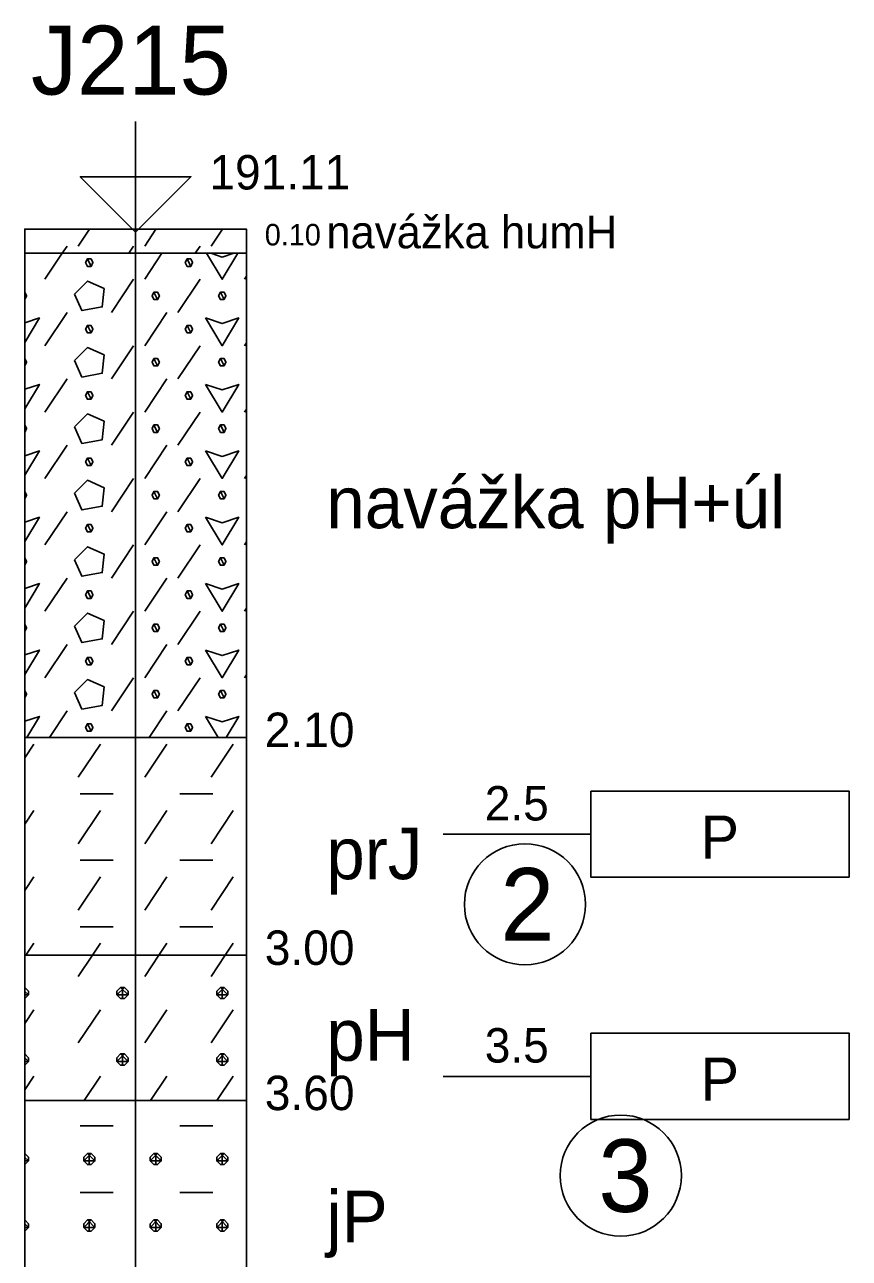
# Model space of a CAD drawing. Extents: x 3042 to 4120, y 576 to 2694.
# Drawn here: x 3710.06 to 3727.08, y 1031.63 to 1057.11 of the extents above; entities that cross this region are included whole.
import ezdxf

# ---------------------------------------------------------------- set-up
doc = ezdxf.new("R2010")
doc.units = 0
for name, color, linetype in [('15', 7, 'Continuous'), ('16', 7, 'Continuous'), ('17', 7, 'Continuous'), ('18', 7, 'Continuous'), ('51', 7, 'Continuous'), ('52', 7, 'Continuous'), ('53', 7, 'Continuous'), ('56', 7, 'Continuous'), ('62', 7, 'Continuous'), ('rozhraní', 7, 'Continuous')]:
    doc.layers.add(name, color=color, linetype=linetype)

msp = doc.modelspace()

# ---------------------------------------------------------------- linework, layer by layer
at = {"layer": '15'}
msp.add_lwpolyline([(3712.347, 1055.113), (3712.347, 1052.827), (3711.204, 1053.97), (3713.49, 1053.97), (3712.347, 1052.827)], dxfattribs=at)
at = {"layer": '18'}
msp.add_line((3712.347, 1007.89), (3712.347, 1052.89), dxfattribs=at)
at = {"layer": '51'}
for p, q in [((3711.163, 1052.539), (3711.397, 1052.89)), ((3712.535, 1052.539), (3712.768, 1052.89)), ((3713.906, 1052.539), (3714.14, 1052.89)), ((3710.477, 1051.854), (3710.835, 1052.39)), ((3710.835, 1052.39), (3710.934, 1052.539)), ((3712.206, 1052.39), (3712.306, 1052.539)), ((3712.535, 1051.854), (3712.892, 1052.39)), ((3713.578, 1052.39), (3713.678, 1052.539)), ((3714.592, 1051.854), (3714.633, 1051.915)), ((3711.849, 1051.168), (3712.306, 1051.854)), ((3713.22, 1051.168), (3713.678, 1051.854)), ((3710.058, 1051.435), (3710.058, 1051.435)), ((3710.477, 1050.482), (3710.934, 1051.168)), ((3712.535, 1050.482), (3712.992, 1051.168)), ((3711.849, 1049.796), (3712.306, 1050.482)), ((3713.22, 1049.796), (3713.678, 1050.482)), ((3714.592, 1050.482), (3714.633, 1050.543)), ((3710.058, 1050.063), (3710.058, 1050.063)), ((3710.477, 1049.11), (3710.934, 1049.796)), ((3712.535, 1049.11), (3712.992, 1049.796)), ((3711.849, 1048.425), (3712.306, 1049.11)), ((3713.22, 1048.425), (3713.678, 1049.11)), ((3714.592, 1049.11), (3714.633, 1049.171)), ((3710.058, 1048.691), (3710.058, 1048.691)), ((3710.477, 1047.739), (3710.934, 1048.425)), ((3712.535, 1047.739), (3712.992, 1048.425)), ((3714.592, 1047.739), (3714.633, 1047.8)), ((3711.849, 1047.053), (3712.306, 1047.739)), ((3713.22, 1047.053), (3713.678, 1047.739)), ((3710.058, 1047.32), (3710.058, 1047.32)), ((3710.477, 1046.367), (3710.934, 1047.053)), ((3712.535, 1046.367), (3712.992, 1047.053)), ((3711.849, 1045.681), (3712.306, 1046.367)), ((3713.22, 1045.681), (3713.678, 1046.367)), ((3714.592, 1046.367), (3714.633, 1046.428)), ((3710.058, 1045.948), (3710.058, 1045.948)), ((3710.477, 1044.996), (3710.934, 1045.681)), ((3712.535, 1044.996), (3712.992, 1045.681)), ((3711.849, 1044.31), (3712.306, 1044.996)), ((3713.22, 1044.31), (3713.678, 1044.996)), ((3714.592, 1044.996), (3714.633, 1045.057)), ((3710.058, 1044.577), (3710.058, 1044.577)), ((3710.477, 1043.624), (3710.934, 1044.31)), ((3712.535, 1043.624), (3712.992, 1044.31)), ((3711.849, 1042.938), (3712.306, 1043.624)), ((3713.22, 1042.938), (3713.678, 1043.624)), ((3714.592, 1043.624), (3714.633, 1043.685)), ((3710.058, 1043.205), (3710.058, 1043.205)), ((3710.569, 1042.39), (3710.934, 1042.938)), ((3712.626, 1042.39), (3712.992, 1042.938)), ((3713.792, 1042.824), (3714.052, 1042.39)), ((3710.061, 1041.971), (3710.249, 1042.252)), ((3711.163, 1041.567), (3711.62, 1042.252)), ((3712.535, 1041.567), (3712.992, 1042.252)), ((3713.906, 1041.567), (3714.363, 1042.252)), ((3711.201, 1041.224), (3711.887, 1041.224)), ((3713.259, 1041.224), (3713.944, 1041.224)), ((3710.061, 1040.599), (3710.249, 1040.881)), ((3711.163, 1040.195), (3711.62, 1040.881)), ((3712.535, 1040.195), (3712.992, 1040.881)), ((3713.906, 1040.195), (3714.363, 1040.881)), ((3711.201, 1039.852), (3711.887, 1039.852)), ((3713.259, 1039.852), (3713.944, 1039.852)), ((3710.061, 1039.227), (3710.249, 1039.509)), ((3711.163, 1038.823), (3711.62, 1039.509)), ((3712.535, 1038.823), (3712.992, 1039.509)), ((3713.906, 1038.823), (3714.363, 1039.509)), ((3711.201, 1038.481), (3711.887, 1038.481)), ((3713.259, 1038.481), (3713.944, 1038.481)), ((3710.084, 1037.89), (3710.249, 1038.138)), ((3711.455, 1037.89), (3711.62, 1038.138)), ((3712.827, 1037.89), (3712.992, 1038.138)), ((3714.198, 1037.89), (3714.363, 1038.138)), ((3711.163, 1037.452), (3711.455, 1037.89)), ((3712.535, 1037.452), (3712.827, 1037.89)), ((3713.906, 1037.452), (3714.198, 1037.89)), ((3710.058, 1037.223), (3710.058, 1037.223)), ((3712.077, 1036.995), (3712.077, 1037.223)), ((3714.135, 1036.995), (3714.135, 1037.223)), ((3710.061, 1036.484), (3710.249, 1036.766)), ((3711.163, 1036.08), (3711.62, 1036.766)), ((3712.535, 1036.08), (3712.992, 1036.766)), ((3713.906, 1036.08), (3714.363, 1036.766)), ((3710.058, 1035.852), (3710.058, 1035.852)), ((3712.077, 1035.623), (3712.077, 1035.852)), ((3714.135, 1035.623), (3714.135, 1035.852)), ((3710.061, 1035.113), (3710.249, 1035.394)), ((3711.284, 1034.89), (3711.62, 1035.394)), ((3712.656, 1034.89), (3712.992, 1035.394)), ((3714.027, 1034.89), (3714.363, 1035.394)), ((3711.201, 1034.366), (3711.887, 1034.366)), ((3713.259, 1034.366), (3713.944, 1034.366)), ((3710.058, 1033.794), (3710.058, 1033.794)), ((3711.392, 1033.566), (3711.392, 1033.794)), ((3712.763, 1033.566), (3712.763, 1033.794)), ((3714.135, 1033.566), (3714.135, 1033.794)), ((3711.201, 1032.994), (3711.887, 1032.994)), ((3713.259, 1032.994), (3713.944, 1032.994)), ((3710.058, 1032.423), (3710.058, 1032.423)), ((3711.392, 1032.194), (3711.392, 1032.423)), ((3712.763, 1032.194), (3712.763, 1032.423)), ((3714.135, 1032.194), (3714.135, 1032.423))]:
    msp.add_line(p, q, dxfattribs=at)
for points in [[(3710.061, 1052.39), (3714.633, 1052.39), (3714.633, 1052.89), (3710.061, 1052.89)], [(3710.061, 1042.39), (3714.633, 1042.39), (3714.633, 1052.39), (3710.061, 1052.39)], [(3710.061, 1037.89), (3714.633, 1037.89), (3714.633, 1042.39), (3710.061, 1042.39)], [(3710.061, 1034.89), (3714.633, 1034.89), (3714.633, 1037.89), (3710.061, 1037.89)], [(3710.061, 1030.39), (3714.633, 1030.39), (3714.633, 1034.89), (3710.061, 1034.89)]]:
    msp.add_lwpolyline(points, close=True, dxfattribs=at)
for points in [[(3713.813, 1052.39), (3714.135, 1051.854), (3714.457, 1052.39)], [(3714.372, 1052.39), (3714.135, 1052.311), (3713.897, 1052.39)], [(3711.354, 1052.273), (3711.315, 1052.197), (3711.354, 1052.12), (3711.43, 1052.12), (3711.468, 1052.197), (3711.43, 1052.273), (3711.354, 1052.273), (3711.43, 1052.12)], [(3713.411, 1052.273), (3713.373, 1052.197), (3713.411, 1052.12), (3713.487, 1052.12), (3713.525, 1052.197), (3713.487, 1052.273), (3713.411, 1052.273), (3713.487, 1052.12)], [(3711.087, 1051.549), (3711.239, 1051.206), (3711.658, 1051.282), (3711.696, 1051.663), (3711.354, 1051.816), (3711.087, 1051.549)], [(3710.058, 1051.435), (3710.058, 1051.435), (3710.096, 1051.511), (3710.058, 1051.587), (3710.058, 1051.587)], [(3712.725, 1051.587), (3712.687, 1051.511), (3712.725, 1051.435), (3712.801, 1051.435), (3712.839, 1051.511), (3712.801, 1051.587), (3712.725, 1051.587), (3712.801, 1051.435)], [(3714.097, 1051.587), (3714.059, 1051.511), (3714.097, 1051.435), (3714.173, 1051.435), (3714.211, 1051.511), (3714.173, 1051.587), (3714.097, 1051.587), (3714.173, 1051.435)], [(3710.061, 1050.55), (3710.363, 1051.054), (3710.061, 1050.953)], [(3711.354, 1050.901), (3711.315, 1050.825), (3711.354, 1050.749), (3711.43, 1050.749), (3711.468, 1050.825), (3711.43, 1050.901), (3711.354, 1050.901), (3711.43, 1050.749)], [(3713.411, 1050.901), (3713.373, 1050.825), (3713.411, 1050.749), (3713.487, 1050.749), (3713.525, 1050.825), (3713.487, 1050.901), (3713.411, 1050.901), (3713.487, 1050.749)], [(3713.792, 1051.054), (3714.135, 1050.482), (3714.478, 1051.054), (3714.135, 1050.939), (3713.792, 1051.054)], [(3711.087, 1050.177), (3711.239, 1049.834), (3711.658, 1049.911), (3711.696, 1050.292), (3711.354, 1050.444), (3711.087, 1050.177)], [(3710.058, 1050.063), (3710.058, 1050.063), (3710.096, 1050.139), (3710.058, 1050.215), (3710.058, 1050.215)], [(3712.725, 1050.215), (3712.687, 1050.139), (3712.725, 1050.063), (3712.801, 1050.063), (3712.839, 1050.139), (3712.801, 1050.215), (3712.725, 1050.215), (3712.801, 1050.063)], [(3714.097, 1050.215), (3714.059, 1050.139), (3714.097, 1050.063), (3714.173, 1050.063), (3714.211, 1050.139), (3714.173, 1050.215), (3714.097, 1050.215), (3714.173, 1050.063)], [(3710.061, 1049.178), (3710.363, 1049.682), (3710.061, 1049.581)], [(3713.792, 1049.682), (3714.135, 1049.11), (3714.478, 1049.682), (3714.135, 1049.568), (3713.792, 1049.682)], [(3711.354, 1049.53), (3711.315, 1049.453), (3711.354, 1049.377), (3711.43, 1049.377), (3711.468, 1049.453), (3711.43, 1049.53), (3711.354, 1049.53), (3711.43, 1049.377)], [(3713.411, 1049.53), (3713.373, 1049.453), (3713.411, 1049.377), (3713.487, 1049.377), (3713.525, 1049.453), (3713.487, 1049.53), (3713.411, 1049.53), (3713.487, 1049.377)], [(3711.087, 1048.806), (3711.239, 1048.463), (3711.658, 1048.539), (3711.696, 1048.92), (3711.354, 1049.072), (3711.087, 1048.806)], [(3710.058, 1048.691), (3710.058, 1048.691), (3710.096, 1048.768), (3710.058, 1048.844), (3710.058, 1048.844)], [(3712.725, 1048.844), (3712.687, 1048.768), (3712.725, 1048.691), (3712.801, 1048.691), (3712.839, 1048.768), (3712.801, 1048.844), (3712.725, 1048.844), (3712.801, 1048.691)], [(3714.097, 1048.844), (3714.059, 1048.768), (3714.097, 1048.691), (3714.173, 1048.691), (3714.211, 1048.768), (3714.173, 1048.844), (3714.097, 1048.844), (3714.173, 1048.691)], [(3710.061, 1047.807), (3710.363, 1048.31), (3710.061, 1048.21)], [(3713.792, 1048.31), (3714.135, 1047.739), (3714.478, 1048.31), (3714.135, 1048.196), (3713.792, 1048.31)], [(3711.354, 1048.158), (3711.315, 1048.082), (3711.354, 1048.006), (3711.43, 1048.006), (3711.468, 1048.082), (3711.43, 1048.158), (3711.354, 1048.158), (3711.43, 1048.006)], [(3713.411, 1048.158), (3713.373, 1048.082), (3713.411, 1048.006), (3713.487, 1048.006), (3713.525, 1048.082), (3713.487, 1048.158), (3713.411, 1048.158), (3713.487, 1048.006)], [(3711.087, 1047.434), (3711.239, 1047.091), (3711.658, 1047.167), (3711.696, 1047.548), (3711.354, 1047.701), (3711.087, 1047.434)], [(3710.058, 1047.32), (3710.058, 1047.32), (3710.096, 1047.396), (3710.058, 1047.472), (3710.058, 1047.472)], [(3712.725, 1047.472), (3712.687, 1047.396), (3712.725, 1047.32), (3712.801, 1047.32), (3712.839, 1047.396), (3712.801, 1047.472), (3712.725, 1047.472), (3712.801, 1047.32)], [(3714.097, 1047.472), (3714.059, 1047.396), (3714.097, 1047.32), (3714.173, 1047.32), (3714.211, 1047.396), (3714.173, 1047.472), (3714.097, 1047.472), (3714.173, 1047.32)], [(3710.061, 1046.435), (3710.363, 1046.939), (3710.061, 1046.838)], [(3711.354, 1046.786), (3711.315, 1046.71), (3711.354, 1046.634), (3711.43, 1046.634), (3711.468, 1046.71), (3711.43, 1046.786), (3711.354, 1046.786), (3711.43, 1046.634)], [(3713.411, 1046.786), (3713.373, 1046.71), (3713.411, 1046.634), (3713.487, 1046.634), (3713.525, 1046.71), (3713.487, 1046.786), (3713.411, 1046.786), (3713.487, 1046.634)], [(3713.792, 1046.939), (3714.135, 1046.367), (3714.478, 1046.939), (3714.135, 1046.824), (3713.792, 1046.939)], [(3711.087, 1046.062), (3711.239, 1045.72), (3711.658, 1045.796), (3711.696, 1046.177), (3711.354, 1046.329), (3711.087, 1046.062)], [(3710.058, 1045.948), (3710.058, 1045.948), (3710.096, 1046.024), (3710.058, 1046.101), (3710.058, 1046.101)], [(3712.725, 1046.101), (3712.687, 1046.024), (3712.725, 1045.948), (3712.801, 1045.948), (3712.839, 1046.024), (3712.801, 1046.101), (3712.725, 1046.101), (3712.801, 1045.948)], [(3714.097, 1046.101), (3714.059, 1046.024), (3714.097, 1045.948), (3714.173, 1045.948), (3714.211, 1046.024), (3714.173, 1046.101), (3714.097, 1046.101), (3714.173, 1045.948)], [(3710.061, 1045.063), (3710.363, 1045.567), (3710.061, 1045.466)], [(3713.792, 1045.567), (3714.135, 1044.996), (3714.478, 1045.567), (3714.135, 1045.453), (3713.792, 1045.567)], [(3711.354, 1045.415), (3711.315, 1045.339), (3711.354, 1045.262), (3711.43, 1045.262), (3711.468, 1045.339), (3711.43, 1045.415), (3711.354, 1045.415), (3711.43, 1045.262)], [(3713.411, 1045.415), (3713.373, 1045.339), (3713.411, 1045.262), (3713.487, 1045.262), (3713.525, 1045.339), (3713.487, 1045.415), (3713.411, 1045.415), (3713.487, 1045.262)], [(3710.058, 1044.577), (3710.058, 1044.577), (3710.096, 1044.653), (3710.058, 1044.729), (3710.058, 1044.729)], [(3711.087, 1044.691), (3711.239, 1044.348), (3711.658, 1044.424), (3711.696, 1044.805), (3711.354, 1044.958), (3711.087, 1044.691)], [(3712.725, 1044.729), (3712.687, 1044.653), (3712.725, 1044.577), (3712.801, 1044.577), (3712.839, 1044.653), (3712.801, 1044.729), (3712.725, 1044.729), (3712.801, 1044.577)], [(3714.097, 1044.729), (3714.059, 1044.653), (3714.097, 1044.577), (3714.173, 1044.577), (3714.211, 1044.653), (3714.173, 1044.729), (3714.097, 1044.729), (3714.173, 1044.577)], [(3710.061, 1043.692), (3710.363, 1044.196), (3710.061, 1044.095)], [(3711.354, 1044.043), (3711.315, 1043.967), (3711.354, 1043.891), (3711.43, 1043.891), (3711.468, 1043.967), (3711.43, 1044.043), (3711.354, 1044.043), (3711.43, 1043.891)], [(3713.411, 1044.043), (3713.373, 1043.967), (3713.411, 1043.891), (3713.487, 1043.891), (3713.525, 1043.967), (3713.487, 1044.043), (3713.411, 1044.043), (3713.487, 1043.891)], [(3713.792, 1044.196), (3714.135, 1043.624), (3714.478, 1044.196), (3714.135, 1044.081), (3713.792, 1044.196)], [(3711.087, 1043.319), (3711.239, 1042.976), (3711.658, 1043.053), (3711.696, 1043.434), (3711.354, 1043.586), (3711.087, 1043.319)], [(3710.058, 1043.205), (3710.058, 1043.205), (3710.096, 1043.281), (3710.058, 1043.357), (3710.058, 1043.357)], [(3712.725, 1043.357), (3712.687, 1043.281), (3712.725, 1043.205), (3712.801, 1043.205), (3712.839, 1043.281), (3712.801, 1043.357), (3712.725, 1043.357), (3712.801, 1043.205)], [(3714.097, 1043.357), (3714.059, 1043.281), (3714.097, 1043.205), (3714.173, 1043.205), (3714.211, 1043.281), (3714.173, 1043.357), (3714.097, 1043.357), (3714.173, 1043.205)], [(3710.103, 1042.39), (3710.363, 1042.824), (3710.061, 1042.723)], [(3714.217, 1042.39), (3714.478, 1042.824), (3714.135, 1042.71), (3713.792, 1042.824)], [(3711.354, 1042.672), (3711.315, 1042.595), (3711.354, 1042.519), (3711.43, 1042.519), (3711.468, 1042.595), (3711.43, 1042.672), (3711.354, 1042.672), (3711.43, 1042.519)], [(3713.411, 1042.672), (3713.373, 1042.595), (3713.411, 1042.519), (3713.487, 1042.519), (3713.525, 1042.595), (3713.487, 1042.672), (3713.411, 1042.672), (3713.487, 1042.519)], [(3710.058, 1036.995), (3710.058, 1036.995), (3710.134, 1037.071), (3710.134, 1037.147), (3710.058, 1037.223), (3710.058, 1037.223)], [(3710.061, 1037.144), (3710.134, 1037.071), (3710.061, 1037.071)], [(3712.039, 1037.223), (3711.963, 1037.147), (3711.963, 1037.071), (3712.039, 1036.995), (3712.116, 1036.995), (3712.192, 1037.071), (3712.192, 1037.147), (3712.116, 1037.223), (3712.039, 1037.223), (3712.192, 1037.071), (3711.963, 1037.071), (3712.116, 1037.223)], [(3714.097, 1037.223), (3714.021, 1037.147), (3714.021, 1037.071), (3714.097, 1036.995), (3714.173, 1036.995), (3714.249, 1037.071), (3714.249, 1037.147), (3714.173, 1037.223), (3714.097, 1037.223), (3714.249, 1037.071), (3714.021, 1037.071), (3714.173, 1037.223)], [(3710.058, 1035.623), (3710.058, 1035.623), (3710.134, 1035.699), (3710.134, 1035.775), (3710.058, 1035.852), (3710.058, 1035.852)], [(3712.039, 1035.852), (3711.963, 1035.775), (3711.963, 1035.699), (3712.039, 1035.623), (3712.116, 1035.623), (3712.192, 1035.699), (3712.192, 1035.775), (3712.116, 1035.852), (3712.039, 1035.852), (3712.192, 1035.699), (3711.963, 1035.699), (3712.116, 1035.852)], [(3714.097, 1035.852), (3714.021, 1035.775), (3714.021, 1035.699), (3714.097, 1035.623), (3714.173, 1035.623), (3714.249, 1035.699), (3714.249, 1035.775), (3714.173, 1035.852), (3714.097, 1035.852), (3714.249, 1035.699), (3714.021, 1035.699), (3714.173, 1035.852)], [(3710.061, 1035.773), (3710.134, 1035.699), (3710.061, 1035.699)], [(3710.058, 1033.566), (3710.058, 1033.566), (3710.134, 1033.642), (3710.134, 1033.718), (3710.058, 1033.794), (3710.058, 1033.794)], [(3711.354, 1033.794), (3711.277, 1033.718), (3711.277, 1033.642), (3711.354, 1033.566), (3711.43, 1033.566), (3711.506, 1033.642), (3711.506, 1033.718), (3711.43, 1033.794), (3711.354, 1033.794), (3711.506, 1033.642), (3711.277, 1033.642), (3711.43, 1033.794)], [(3712.725, 1033.794), (3712.649, 1033.718), (3712.649, 1033.642), (3712.725, 1033.566), (3712.801, 1033.566), (3712.878, 1033.642), (3712.878, 1033.718), (3712.801, 1033.794), (3712.725, 1033.794), (3712.878, 1033.642), (3712.649, 1033.642), (3712.801, 1033.794)], [(3714.097, 1033.794), (3714.021, 1033.718), (3714.021, 1033.642), (3714.097, 1033.566), (3714.173, 1033.566), (3714.249, 1033.642), (3714.249, 1033.718), (3714.173, 1033.794), (3714.097, 1033.794), (3714.249, 1033.642), (3714.021, 1033.642), (3714.173, 1033.794)], [(3710.061, 1033.715), (3710.134, 1033.642), (3710.061, 1033.642)], [(3710.058, 1032.194), (3710.058, 1032.194), (3710.134, 1032.27), (3710.134, 1032.346), (3710.058, 1032.423), (3710.058, 1032.423)], [(3710.061, 1032.344), (3710.134, 1032.27), (3710.061, 1032.27)], [(3711.354, 1032.423), (3711.277, 1032.346), (3711.277, 1032.27), (3711.354, 1032.194), (3711.43, 1032.194), (3711.506, 1032.27), (3711.506, 1032.346), (3711.43, 1032.423), (3711.354, 1032.423), (3711.506, 1032.27), (3711.277, 1032.27), (3711.43, 1032.423)], [(3712.725, 1032.423), (3712.649, 1032.346), (3712.649, 1032.27), (3712.725, 1032.194), (3712.801, 1032.194), (3712.878, 1032.27), (3712.878, 1032.346), (3712.801, 1032.423), (3712.725, 1032.423), (3712.878, 1032.27), (3712.649, 1032.27), (3712.801, 1032.423)], [(3714.097, 1032.423), (3714.021, 1032.346), (3714.021, 1032.27), (3714.097, 1032.194), (3714.173, 1032.194), (3714.249, 1032.27), (3714.249, 1032.346), (3714.173, 1032.423), (3714.097, 1032.423), (3714.249, 1032.27), (3714.021, 1032.27), (3714.173, 1032.423)]]:
    msp.add_lwpolyline(points, dxfattribs=at)
at = {"layer": '53'}
for p, q in [((3710.061, 1052.89), (3714.633, 1052.89)), ((3710.061, 1052.89), (3710.061, 1007.89)), ((3714.633, 1052.89), (3714.633, 1007.89)), ((3710.061, 1052.39), (3714.633, 1052.39)), ((3710.061, 1042.39), (3714.633, 1042.39)), ((3710.061, 1037.89), (3714.633, 1037.89)), ((3710.061, 1034.89), (3714.633, 1034.89))]:
    msp.add_line(p, q, dxfattribs=at)
at = {"layer": '56'}
for p, q in [((3712.347, 1053.271), (3712.347, 1052.509)), ((3711.966, 1052.89), (3712.728, 1052.89)), ((3712.347, 1052.771), (3712.347, 1052.009)), ((3711.966, 1052.39), (3712.728, 1052.39)), ((3712.347, 1042.771), (3712.347, 1042.009)), ((3711.966, 1042.39), (3712.728, 1042.39)), ((3712.347, 1038.271), (3712.347, 1037.509)), ((3711.966, 1037.89), (3712.728, 1037.89)), ((3712.347, 1035.271), (3712.347, 1034.509)), ((3711.966, 1034.89), (3712.728, 1034.89))]:
    msp.add_line(p, q, dxfattribs=at)
at = {"layer": '62'}
for p, q in [((3718.697, 1040.39), (3721.745, 1040.39)), ((3718.697, 1035.39), (3721.745, 1035.39))]:
    msp.add_line(p, q, dxfattribs=at)
for points in [[(3727.079, 1039.501), (3721.745, 1039.501), (3721.745, 1041.279), (3727.079, 1041.279), (3727.079, 1039.501)], [(3727.079, 1034.501), (3721.745, 1034.501), (3721.745, 1036.279), (3727.079, 1036.279), (3727.079, 1034.501)]]:
    msp.add_lwpolyline(points, dxfattribs=at)
at = {"layer": 'rozhraní'}
for centre in [(3720.384, 1038.943), (3720.384, 1038.943), (3722.362, 1033.34)]:
    msp.add_circle(centre, 1.25, dxfattribs=at)

# ---------------------------------------------------------------- texts
at = {"layer": '16'}
msp.add_text('J215', height=1.4224, dxfattribs=at).set_placement((3710.188, 1055.669))
at = {"layer": '17'}
msp.add_text('191.11', height=0.7112, dxfattribs=at).set_placement((3713.871, 1053.708))
at = {"layer": '52'}
for s, height, p in [('navážka humH', 0.6731, (3716.284, 1052.493)), ('0.10', 0.4445, (3715.014, 1052.552)), ('navážka pH+úl', 1.0668, (3716.284, 1046.712)), ('2.10', 0.7112, (3715.014, 1042.192)), ('prJ', 1.0668, (3716.284, 1039.462)), ('3.00', 0.7112, (3715.014, 1037.692)), ('pH', 1.0668, (3716.284, 1035.712)), ('3.60', 0.7112, (3715.014, 1034.692)), ('jP', 1.0668, (3716.284, 1031.962))]:
    msp.add_text(s, height=height, dxfattribs=at).set_placement(p)
at = {"layer": '62'}
for s, height, p in [('2.5', 0.7112, (3719.554, 1040.675)), ('P', 0.889, (3724.01, 1039.888)), ('3.5', 0.7112, (3719.554, 1035.675)), ('P', 0.889, (3724.01, 1034.888))]:
    msp.add_text(s, height=height, dxfattribs=at).set_placement(p)
at = {"layer": 'rozhraní'}
for s, p in [('2', (3719.876, 1038.193)), ('3', (3721.9, 1032.59))]:
    msp.add_text(s, height=1.5, dxfattribs=at).set_placement(p)

doc.saveas('drawing.dxf')
